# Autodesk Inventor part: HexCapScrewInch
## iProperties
Author: Administrator
Shininess: 20.0
PropertySet Name: _Private Model Information
Created: 2000-12
Part Number: HexCapScrewInch
Document SubType Name: Modeling
Designer: Administrator
Control State: 0
Master: False
Checked Out: False
PropertySet Name: Design Tracking Control
Density: 0.0
Volumn: 0.0
Area: 0.0
PropertySet Name: Model Information
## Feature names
1. Extrusion1
2. Extrusion2
3. Revolution1
4. Extrusion3
5. Chamfer1
